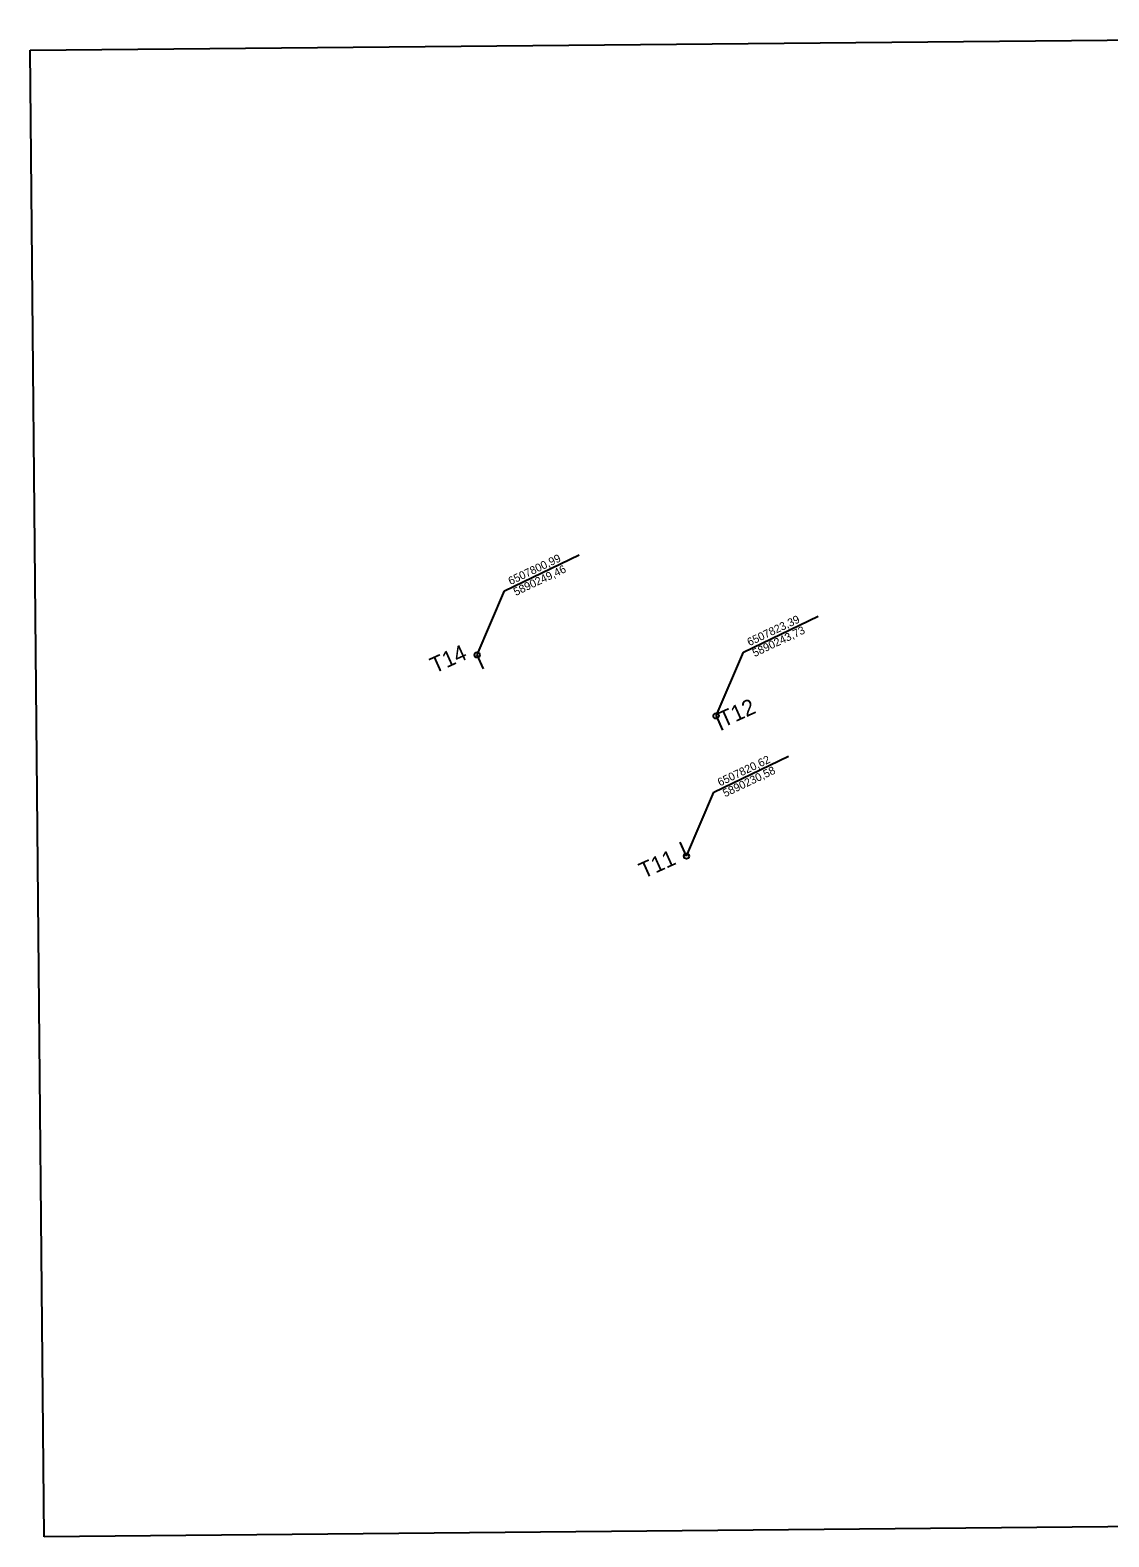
# Model space of a CAD drawing. Extents: x 6505045 to 6511721, y 5887996 to 5893535.
# Drawn here: x 6507759.1 to 6507860.2, y 5890166.7 to 5890308.1 of the extents above; entities that cross this region are included whole.
import ezdxf

# ---------------------------------------------------------------- set-up
doc = ezdxf.new("R2010")
doc.units = 0
for name, color, linetype in [('P_1 tablica LCD', 7, 'Continuous'), ('P_2 tablice LCD', 7, 'Continuous'), ('P_lokalizacja slupka', 7, 'Continuous'), ('P_opisy', 7, 'Continuous'), ('P_tabela', 7, 'Continuous'), ('P_wsporzedne', 7, 'Continuous')]:
    doc.layers.add(name, color=color, linetype=linetype)

msp = doc.modelspace()

# ---------------------------------------------------------------- linework, layer by layer
at = {"layer": 'P_1 tablica LCD'}
msp.add_line((6507801.59, 5890248.15), (6507800.99, 5890249.46), dxfattribs=at)
at = {"layer": 'P_2 tablice LCD'}
for p, q in [((6507823.39, 5890243.73), (6507823.99, 5890242.41)), ((6507820.62, 5890230.58), (6507820.01, 5890231.9))]:
    msp.add_line(p, q, dxfattribs=at)
at = {"layer": 'P_lokalizacja slupka'}
for centre in [(6507800.99, 5890249.46), (6507823.39, 5890243.73), (6507820.62, 5890230.58)]:
    msp.add_circle(centre, 0.25, dxfattribs=at)
at = {"layer": 'P_tabela'}
for p, q in [((6507759.07, 5890306.18), (6507960.06, 5890308.06)), ((6507759.07, 5890306.18), (6507960.06, 5890308.06)), ((6507759.07, 5890306.18), (6507960.06, 5890308.06)), ((6507760.38, 5890166.74), (6507759.07, 5890306.18)), ((6507760.38, 5890166.74), (6507759.07, 5890306.18)), ((6507760.38, 5890166.74), (6507759.07, 5890306.18)), ((6507961.36, 5890168.61), (6507760.38, 5890166.74)), ((6507961.36, 5890168.61), (6507760.38, 5890166.74)), ((6507961.36, 5890168.61), (6507760.38, 5890166.74))]:
    msp.add_line(p, q, dxfattribs=at)
at = {"layer": 'P_wsporzedne'}
for p, q in [((6507803.55, 5890255.46), (6507810.55, 5890258.84)), ((6507800.99, 5890249.46), (6507803.55, 5890255.46)), ((6507825.95, 5890249.72), (6507832.95, 5890253.1)), ((6507823.39, 5890243.73), (6507825.95, 5890249.72)), ((6507823.18, 5890236.57), (6507830.18, 5890239.95)), ((6507820.62, 5890230.58), (6507823.18, 5890236.57))]:
    msp.add_line(p, q, dxfattribs=at)

# ---------------------------------------------------------------- texts
at = {"layer": 'P_opisy'}
for s, p in [('T14', (6507797, 5890247.7)), ('T12', (6507824.08, 5890242.64)), ('T11', (6507816.59, 5890228.45))]:
    msp.add_text(s, height=1.501, rotation=24.2052, dxfattribs=at).set_placement(p)
at = {"layer": 'P_wsporzedne'}
for s, p in [('6507800,99', (6507804.12, 5890256)), ('5890249,46', (6507804.61, 5890254.98)), ('6507823,39', (6507826.52, 5890250.27)), ('5890243,73', (6507827.01, 5890249.25)), ('6507820,62', (6507823.75, 5890237.12)), ('5890230,58', (6507824.24, 5890236.1))]:
    msp.add_text(s, height=0.751, rotation=25.405, dxfattribs=at).set_placement(p)

doc.saveas('drawing.dxf')
